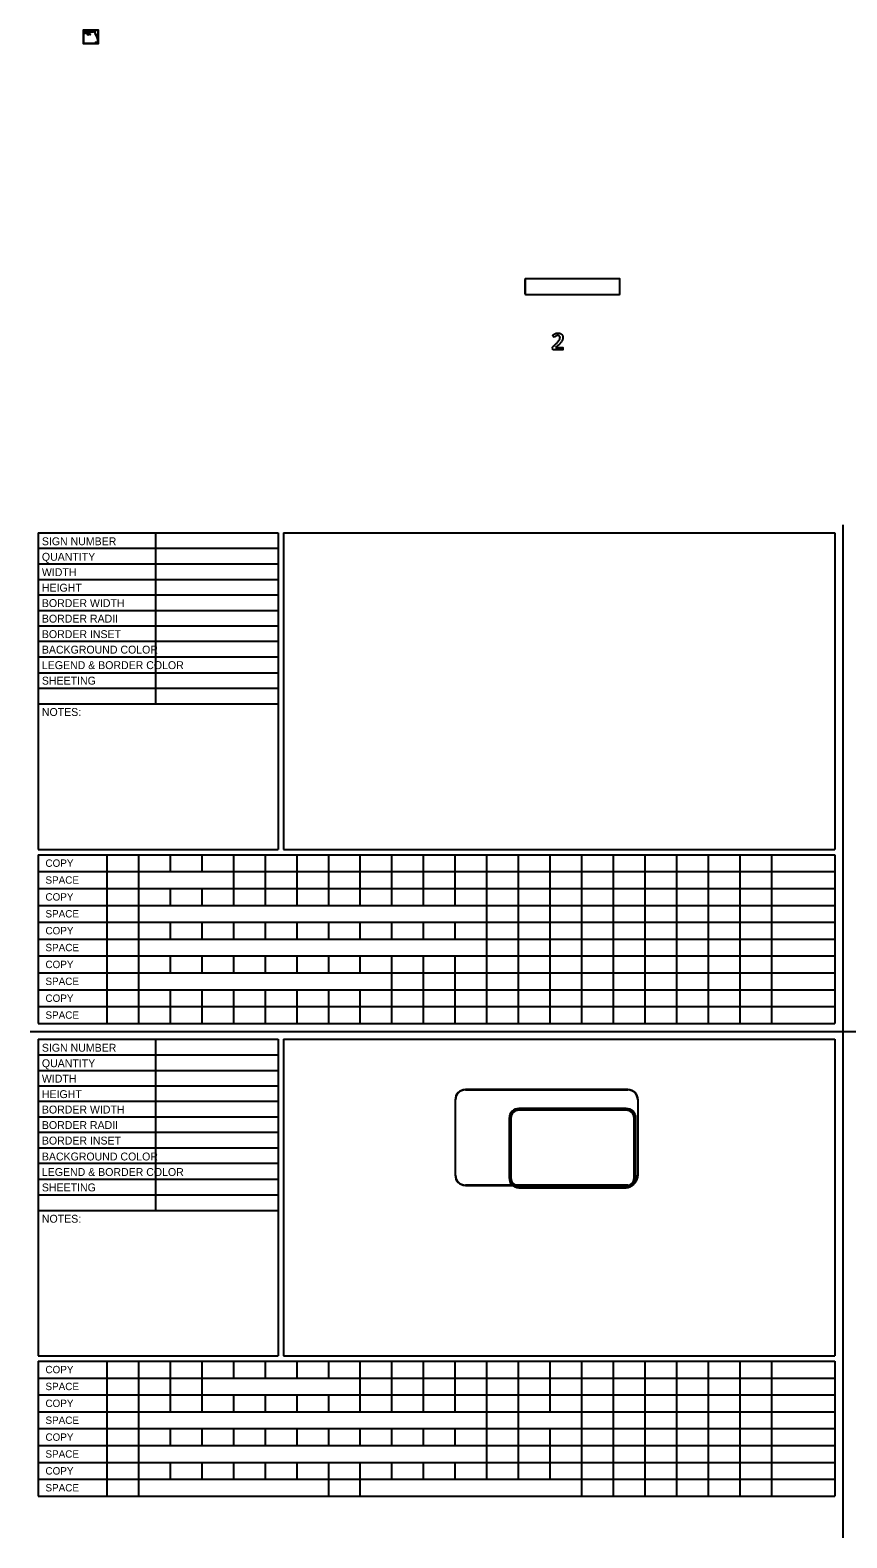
# Model space of a CAD drawing. Extents: x 10268197 to 10268511, y 2141503 to 2142677.
# Drawn here: x 10268317.7 to 10268395.1, y 2142380.3 to 2142523.2 of the extents above; entities that cross this region are included whole.
import ezdxf

# ---------------------------------------------------------------- set-up
doc = ezdxf.new("R2010")
doc.units = 0
for name, color, linetype in [('GSColorFill', 7, 'Continuous'), ('GSOutline', 7, 'Continuous'), ('SheetBorder_dp', 7, 'Continuous'), ('SumBoxLines_dp', 7, 'Continuous'), ('SumBoxLinesMin_dp', 7, 'Continuous'), ('TextMisc', 7, 'Continuous')]:
    doc.layers.add(name, color=color, linetype=linetype)

msp = doc.modelspace()

# ---------------------------------------------------------------- linework, layer by layer
at = {"layer": 'GSColorFill'}
for p, q in [((10268358, 2142421.8), (10268358, 2142414.65)), ((10268358, 2142421.8), (10268358, 2142414.65)), ((10268358.02, 2142414.65), (10268358.02, 2142421.8)), ((10268374.36, 2142422.76), (10268358.96, 2142422.76)), ((10268374.36, 2142422.76), (10268358.96, 2142422.76)), ((10268358.96, 2142422.73), (10268374.36, 2142422.73)), ((10268375.29, 2142421.8), (10268375.29, 2142414.65)), ((10268375.32, 2142414.65), (10268375.32, 2142421.8)), ((10268375.32, 2142414.65), (10268375.32, 2142421.8)), ((10268358.96, 2142413.68), (10268358.96, 2142413.71)), ((10268374.36, 2142413.71), (10268358.96, 2142413.71)), ((10268358.96, 2142413.71), (10268358.96, 2142413.68)), ((10268358.96, 2142413.68), (10268374.36, 2142413.68)), ((10268358.96, 2142413.68), (10268374.36, 2142413.68))]:
    msp.add_line(p, q, dxfattribs=at)
for centre, radius, start, end in [((10268358.96, 2142421.8), 0.963, 90, 180), ((10268358.96, 2142421.8), 0.963, 90, 180), ((10268358.96, 2142421.8), 0.935, 90, 180), ((10268374.36, 2142421.8), 0.963, 0, 90), ((10268374.36, 2142421.8), 0.963, 0, 90), ((10268374.36, 2142421.8), 0.935, 0, 90), ((10268358.96, 2142414.65), 0.963, 180, 270), ((10268358.96, 2142414.65), 0.963, 180, 270), ((10268358.96, 2142414.65), 0.935, 180, 270), ((10268374.36, 2142414.65), 0.963, 270, 0), ((10268374.36, 2142414.65), 0.963, 270, 0), ((10268374.36, 2142414.65), 0.935, 270, 0)]:
    msp.add_arc(centre, radius, start, end, dxfattribs=at)
at = {"layer": 'GSOutline'}
for p, q in [((10268322.74, 2142523.14), (10268322.74, 2142521.96)), ((10268322.75, 2142523.14), (10268322.75, 2142521.96)), ((10268324.17, 2142523.18), (10268322.78, 2142523.18)), ((10268324.17, 2142523.17), (10268322.78, 2142523.17)), ((10268324.21, 2142521.96), (10268324.21, 2142523.14)), ((10268324.21, 2142521.96), (10268324.21, 2142523.14)), ((10268322.78, 2142521.92), (10268324.17, 2142521.92)), ((10268322.78, 2142521.91), (10268324.17, 2142521.91)), ((10268364.61, 2142499.54), (10268364.61, 2142498.2)), ((10268364.63, 2142499.54), (10268364.63, 2142498.2)), ((10268373.53, 2142499.62), (10268364.7, 2142499.62)), ((10268373.53, 2142499.6), (10268364.7, 2142499.6)), ((10268373.59, 2142498.2), (10268373.59, 2142499.54)), ((10268373.61, 2142498.2), (10268373.61, 2142499.54)), ((10268364.7, 2142498.14), (10268373.53, 2142498.14)), ((10268364.7, 2142498.12), (10268373.53, 2142498.12)), ((10268363.11, 2142420.06), (10268363.11, 2142414.39)), ((10268363.28, 2142420.06), (10268363.28, 2142414.39)), ((10268374.2, 2142420.98), (10268364.03, 2142420.98)), ((10268374.2, 2142420.81), (10268364.03, 2142420.81)), ((10268374.95, 2142414.39), (10268374.95, 2142420.06)), ((10268375.12, 2142414.39), (10268375.12, 2142420.06)), ((10268364.03, 2142413.64), (10268374.2, 2142413.64)), ((10268364.03, 2142413.47), (10268374.2, 2142413.47))]:
    msp.add_line(p, q, dxfattribs=at)
for points in [[(10268322.78, 2142523.14), (10268322.78, 2142521.96), (10268324.17, 2142521.96), (10268324.17, 2142523.14)], [(10268323.88, 2142521.99), (10268323.94, 2142521.96), (10268324.02, 2142521.97), (10268324.14, 2142522.1), (10268324.14, 2142522.28), (10268324.09, 2142522.5), (10268324.01, 2142522.62), (10268324.02, 2142522.68), (10268323.93, 2142522.83), (10268323.87, 2142523.11), (10268323.74, 2142523.11), (10268323.72, 2142523.08), (10268323.26, 2142523.08), (10268323.25, 2142523.12), (10268322.81, 2142523.14), (10268322.82, 2142522.9), (10268322.94, 2142522.89), (10268322.97, 2142522.91), (10268323.1, 2142522.85), (10268323.2, 2142522.74), (10268323.34, 2142522.8), (10268323.42, 2142522.75), (10268323.44, 2142522.79), (10268323.35, 2142522.85), (10268323.22, 2142522.8), (10268323.13, 2142522.88), (10268322.97, 2142522.95), (10268322.93, 2142522.94), (10268322.87, 2142522.94), (10268322.85, 2142523.09), (10268323.21, 2142523.08), (10268323.23, 2142523.03), (10268323.74, 2142523.03), (10268323.76, 2142523.07), (10268323.84, 2142523.07), (10268323.89, 2142522.81), (10268323.97, 2142522.67), (10268323.97, 2142522.61), (10268324.05, 2142522.48), (10268324.1, 2142522.28), (10268324.1, 2142522.11), (10268324, 2142522.01), (10268323.95, 2142522), (10268323.91, 2142522.03)]]:
    msp.add_lwpolyline(points, close=True, dxfattribs=at)
for points in [[(10268367.25, 2142492.88), (10268367.21, 2142493.13)], [(10268367.38, 2142494.04), (10268367.23, 2142494.24)], [(10268367.51, 2142493.11), (10268368.21, 2142493.11), (10268368.21, 2142492.88), (10268367.25, 2142492.88)]]:
    msp.add_lwpolyline(points, dxfattribs=at)
for centre, radius, start, end in [((10268322.78, 2142523.14), 0.0439, 90, 180), ((10268322.78, 2142523.14), 0.0352, 90, 180), ((10268324.17, 2142523.14), 0.0439, 0, 90), ((10268324.17, 2142523.14), 0.0352, 0, 90), ((10268322.78, 2142521.96), 0.0439, 180, 270), ((10268322.78, 2142521.96), 0.0352, 180, 270), ((10268324.17, 2142521.96), 0.0352, 270, 0), ((10268324.17, 2142521.96), 0.0439, 270, 0), ((10268364.7, 2142499.54), 0.0833, 90, 180), ((10268364.7, 2142499.54), 0.0625, 90, 180), ((10268373.53, 2142499.54), 0.0833, 0, 90), ((10268373.53, 2142499.54), 0.0625, 0, 90), ((10268364.7, 2142498.2), 0.0833, 180, 270), ((10268364.7, 2142498.2), 0.0625, 180, 270), ((10268373.53, 2142498.2), 0.0833, 270, 0), ((10268373.53, 2142498.2), 0.0625, 270, 0), ((10268364.03, 2142420.06), 0.917, 90, 180), ((10268364.03, 2142420.06), 0.75, 90, 180), ((10268374.2, 2142420.06), 0.917, 0, 90), ((10268374.2, 2142420.06), 0.75, 0, 90), ((10268364.03, 2142414.39), 0.917, 180, 270), ((10268364.03, 2142414.39), 0.75, 180, 270), ((10268374.2, 2142414.39), 0.917, 270, 0), ((10268374.2, 2142414.39), 0.75, 270, 0)]:
    msp.add_arc(centre, radius, start, end, dxfattribs=at)
for points in [[(10268367.23, 2142494.24), (10268367.25, 2142494.26), (10268367.29, 2142494.3), (10268367.34, 2142494.34), (10268367.39, 2142494.37), (10268367.43, 2142494.39), (10268367.47, 2142494.41), (10268367.51, 2142494.43), (10268367.56, 2142494.44), (10268367.6, 2142494.45), (10268367.66, 2142494.46), (10268367.71, 2142494.46), (10268367.74, 2142494.47)], [(10268367.74, 2142494.47), (10268367.76, 2142494.46), (10268367.81, 2142494.46), (10268367.87, 2142494.45), (10268367.93, 2142494.44), (10268367.98, 2142494.42), (10268368.02, 2142494.4), (10268368.06, 2142494.37), (10268368.08, 2142494.36), (10268368.1, 2142494.34), (10268368.12, 2142494.31), (10268368.14, 2142494.28), (10268368.16, 2142494.25), (10268368.17, 2142494.22), (10268368.18, 2142494.2), (10268368.2, 2142494.15), (10268368.2, 2142494.1), (10268368.2, 2142494.06), (10268368.2, 2142494.04)], [(10268367.21, 2142493.13), (10268367.27, 2142493.18), (10268367.37, 2142493.27), (10268367.51, 2142493.41), (10268367.64, 2142493.53), (10268367.73, 2142493.63), (10268367.8, 2142493.72), (10268367.84, 2142493.78), (10268367.88, 2142493.84), (10268367.9, 2142493.88), (10268367.91, 2142493.91), (10268367.92, 2142493.96), (10268367.93, 2142494), (10268367.93, 2142494.02), (10268367.93, 2142494.03)], [(10268367.72, 2142494.23), (10268367.72, 2142494.23), (10268367.69, 2142494.23), (10268367.65, 2142494.23), (10268367.61, 2142494.21), (10268367.57, 2142494.2), (10268367.54, 2142494.18), (10268367.49, 2142494.15), (10268367.43, 2142494.1), (10268367.39, 2142494.06), (10268367.38, 2142494.04)], [(10268368.2, 2142494.04), (10268368.2, 2142494.02), (10268368.2, 2142493.97), (10268368.19, 2142493.91), (10268368.17, 2142493.84), (10268368.14, 2142493.78), (10268368.11, 2142493.71), (10268368.04, 2142493.62), (10268367.96, 2142493.52), (10268367.84, 2142493.4), (10268367.69, 2142493.26), (10268367.57, 2142493.16), (10268367.51, 2142493.11)], [(10268367.93, 2142494.03), (10268367.93, 2142494.03), (10268367.93, 2142494.05), (10268367.92, 2142494.08), (10268367.92, 2142494.1), (10268367.91, 2142494.12), (10268367.91, 2142494.13), (10268367.9, 2142494.15), (10268367.89, 2142494.16), (10268367.88, 2142494.17), (10268367.87, 2142494.18), (10268367.86, 2142494.19), (10268367.85, 2142494.2), (10268367.83, 2142494.21), (10268367.82, 2142494.22), (10268367.81, 2142494.22), (10268367.78, 2142494.23), (10268367.75, 2142494.23), (10268367.73, 2142494.23), (10268367.72, 2142494.23)]]:
    msp.add_open_spline(points, degree=3, dxfattribs=at)
at = {"layer": 'SheetBorder_dp'}
for p, q in [((10268394.73, 2142476.28), (10268394.73, 2142380.28)), ((10268317.73, 2142428.28), (10268471.73, 2142428.28))]:
    msp.add_line(p, q, dxfattribs=at)
at = {"layer": 'SumBoxLines_dp'}
for p, q in [((10268318.48, 2142475.53), (10268318.48, 2142445.53)), ((10268318.48, 2142475.53), (10268341.23, 2142475.53)), ((10268329.6, 2142475.53), (10268329.6, 2142459.34)), ((10268341.23, 2142475.53), (10268341.23, 2142445.53)), ((10268341.73, 2142475.53), (10268341.73, 2142445.53)), ((10268341.73, 2142475.53), (10268393.98, 2142475.53)), ((10268393.98, 2142475.53), (10268393.98, 2142445.53)), ((10268318.48, 2142474.07), (10268341.23, 2142474.07)), ((10268318.48, 2142472.59), (10268341.23, 2142472.59)), ((10268318.48, 2142471.12), (10268341.23, 2142471.12)), ((10268318.48, 2142469.66), (10268341.23, 2142469.66)), ((10268318.48, 2142468.19), (10268341.23, 2142468.19)), ((10268318.48, 2142466.73), (10268341.23, 2142466.73)), ((10268318.48, 2142465.26), (10268341.23, 2142465.26)), ((10268318.48, 2142463.79), (10268341.23, 2142463.79)), ((10268318.48, 2142462.28), (10268341.23, 2142462.28)), ((10268318.48, 2142460.81), (10268341.23, 2142460.81)), ((10268318.48, 2142459.34), (10268341.23, 2142459.34)), ((10268318.48, 2142445.53), (10268341.23, 2142445.53)), ((10268318.48, 2142445.03), (10268393.98, 2142445.03)), ((10268318.48, 2142445.03), (10268318.48, 2142429.03)), ((10268324.98, 2142445.03), (10268324.98, 2142429.03)), ((10268327.98, 2142445.03), (10268327.98, 2142429.03)), ((10268330.98, 2142445.03), (10268330.98, 2142443.43)), ((10268333.98, 2142445.03), (10268333.98, 2142443.43)), ((10268336.98, 2142445.03), (10268336.98, 2142441.83)), ((10268339.98, 2142445.03), (10268339.98, 2142441.83)), ((10268341.73, 2142445.53), (10268393.98, 2142445.53)), ((10268342.98, 2142445.03), (10268342.98, 2142441.83)), ((10268345.98, 2142445.03), (10268345.98, 2142441.83)), ((10268348.98, 2142445.03), (10268348.98, 2142441.83)), ((10268351.98, 2142445.03), (10268351.98, 2142443.43)), ((10268354.98, 2142445.03), (10268354.98, 2142443.43)), ((10268357.98, 2142445.03), (10268357.98, 2142443.43)), ((10268360.98, 2142445.03), (10268360.98, 2142441.83)), ((10268363.98, 2142445.03), (10268363.98, 2142441.83)), ((10268366.98, 2142445.03), (10268366.98, 2142441.83)), ((10268369.98, 2142445.03), (10268369.98, 2142441.83)), ((10268372.98, 2142445.03), (10268372.98, 2142443.43)), ((10268375.98, 2142445.03), (10268375.98, 2142443.43)), ((10268378.98, 2142445.03), (10268378.98, 2142443.43)), ((10268381.98, 2142445.03), (10268381.98, 2142443.43)), ((10268384.98, 2142445.03), (10268384.98, 2142443.43)), ((10268387.98, 2142445.03), (10268387.98, 2142443.43)), ((10268393.98, 2142445.03), (10268393.98, 2142429.03)), ((10268351.98, 2142443.43), (10268351.98, 2142440.23)), ((10268354.98, 2142443.43), (10268354.98, 2142440.23)), ((10268357.98, 2142443.43), (10268357.98, 2142440.23)), ((10268372.98, 2142443.43), (10268372.98, 2142429.03)), ((10268375.98, 2142443.43), (10268375.98, 2142429.03)), ((10268378.98, 2142443.43), (10268378.98, 2142437.03)), ((10268381.98, 2142443.43), (10268381.98, 2142437.03)), ((10268384.98, 2142443.43), (10268384.98, 2142437.03)), ((10268387.98, 2142443.43), (10268387.98, 2142429.03)), ((10268318.48, 2142441.83), (10268393.98, 2142441.83)), ((10268330.98, 2142441.83), (10268330.98, 2142440.23)), ((10268333.98, 2142441.83), (10268333.98, 2142440.23)), ((10268336.98, 2142441.83), (10268336.98, 2142440.23)), ((10268339.98, 2142441.83), (10268339.98, 2142440.23)), ((10268342.98, 2142441.83), (10268342.98, 2142440.23)), ((10268345.98, 2142441.83), (10268345.98, 2142440.23)), ((10268348.98, 2142441.83), (10268348.98, 2142440.23)), ((10268360.98, 2142441.83), (10268360.98, 2142438.63)), ((10268363.98, 2142441.83), (10268363.98, 2142438.63)), ((10268366.98, 2142441.83), (10268366.98, 2142437.03)), ((10268369.98, 2142441.83), (10268369.98, 2142437.03)), ((10268318.48, 2142438.63), (10268393.98, 2142438.63)), ((10268330.98, 2142438.63), (10268330.98, 2142437.03)), ((10268333.98, 2142438.63), (10268333.98, 2142437.03)), ((10268336.98, 2142438.63), (10268336.98, 2142437.03)), ((10268339.98, 2142438.63), (10268339.98, 2142437.03)), ((10268342.98, 2142438.63), (10268342.98, 2142437.03)), ((10268345.98, 2142438.63), (10268345.98, 2142437.03)), ((10268348.98, 2142438.63), (10268348.98, 2142437.03)), ((10268351.98, 2142438.63), (10268351.98, 2142437.03)), ((10268354.98, 2142438.63), (10268354.98, 2142437.03)), ((10268357.98, 2142438.63), (10268357.98, 2142437.03)), ((10268360.98, 2142438.63), (10268360.98, 2142429.03)), ((10268363.98, 2142438.63), (10268363.98, 2142429.03)), ((10268366.98, 2142437.03), (10268366.98, 2142429.03)), ((10268369.98, 2142437.03), (10268369.98, 2142429.03)), ((10268378.98, 2142437.03), (10268378.98, 2142429.03)), ((10268381.98, 2142437.03), (10268381.98, 2142429.03)), ((10268384.98, 2142437.03), (10268384.98, 2142429.03)), ((10268318.48, 2142435.43), (10268393.98, 2142435.43)), ((10268330.98, 2142435.43), (10268330.98, 2142433.83)), ((10268333.98, 2142435.43), (10268333.98, 2142433.83)), ((10268336.98, 2142435.43), (10268336.98, 2142433.83)), ((10268339.98, 2142435.43), (10268339.98, 2142433.83)), ((10268342.98, 2142435.43), (10268342.98, 2142433.83)), ((10268345.98, 2142435.43), (10268345.98, 2142433.83)), ((10268348.98, 2142435.43), (10268348.98, 2142433.83)), ((10268351.98, 2142435.43), (10268351.98, 2142429.03)), ((10268354.98, 2142435.43), (10268354.98, 2142429.03)), ((10268357.98, 2142435.43), (10268357.98, 2142429.03)), ((10268318.48, 2142432.23), (10268393.98, 2142432.23)), ((10268330.98, 2142432.23), (10268330.98, 2142429.03)), ((10268333.98, 2142432.23), (10268333.98, 2142429.03)), ((10268336.98, 2142432.23), (10268336.98, 2142429.03)), ((10268339.98, 2142432.23), (10268339.98, 2142429.03)), ((10268342.98, 2142432.23), (10268342.98, 2142429.03)), ((10268345.98, 2142432.23), (10268345.98, 2142429.03)), ((10268348.98, 2142432.23), (10268348.98, 2142429.03)), ((10268318.48, 2142429.03), (10268393.98, 2142429.03)), ((10268318.48, 2142427.53), (10268318.48, 2142397.53)), ((10268318.48, 2142427.53), (10268341.23, 2142427.53)), ((10268329.6, 2142427.53), (10268329.6, 2142411.31)), ((10268341.23, 2142427.53), (10268341.23, 2142397.53)), ((10268341.73, 2142427.53), (10268341.73, 2142397.53)), ((10268341.73, 2142427.53), (10268393.98, 2142427.53)), ((10268393.98, 2142427.53), (10268393.98, 2142397.53)), ((10268318.48, 2142426.07), (10268341.23, 2142426.07)), ((10268318.48, 2142424.59), (10268341.23, 2142424.59)), ((10268318.48, 2142423.12), (10268341.23, 2142423.12)), ((10268318.48, 2142421.66), (10268341.23, 2142421.66)), ((10268318.48, 2142420.19), (10268341.23, 2142420.19)), ((10268318.48, 2142418.73), (10268341.23, 2142418.73)), ((10268318.48, 2142417.26), (10268341.23, 2142417.26)), ((10268318.48, 2142415.79), (10268341.23, 2142415.79)), ((10268318.48, 2142414.28), (10268341.23, 2142414.28)), ((10268318.48, 2142412.8), (10268341.23, 2142412.8)), ((10268318.48, 2142411.31), (10268341.23, 2142411.31)), ((10268318.48, 2142397.53), (10268341.23, 2142397.53)), ((10268341.73, 2142397.53), (10268393.98, 2142397.53)), ((10268318.48, 2142397.03), (10268393.98, 2142397.03)), ((10268318.48, 2142397.03), (10268318.48, 2142384.23)), ((10268324.98, 2142397.03), (10268324.98, 2142384.23)), ((10268327.98, 2142397.03), (10268327.98, 2142384.23)), ((10268330.98, 2142397.03), (10268330.98, 2142393.83)), ((10268333.98, 2142397.03), (10268333.98, 2142393.83)), ((10268336.98, 2142397.03), (10268336.98, 2142395.43)), ((10268339.98, 2142397.03), (10268339.98, 2142395.43)), ((10268342.98, 2142397.03), (10268342.98, 2142395.43)), ((10268345.98, 2142397.03), (10268345.98, 2142395.43)), ((10268348.98, 2142397.03), (10268348.98, 2142393.83)), ((10268351.98, 2142397.03), (10268351.98, 2142393.83)), ((10268354.98, 2142397.03), (10268354.98, 2142393.83)), ((10268357.98, 2142397.03), (10268357.98, 2142395.43)), ((10268360.98, 2142397.03), (10268360.98, 2142395.43)), ((10268363.98, 2142397.03), (10268363.98, 2142393.83)), ((10268366.98, 2142397.03), (10268366.98, 2142393.83)), ((10268369.98, 2142397.03), (10268369.98, 2142395.43)), ((10268372.98, 2142397.03), (10268372.98, 2142395.43)), ((10268375.98, 2142397.03), (10268375.98, 2142395.43)), ((10268378.98, 2142397.03), (10268378.98, 2142395.43)), ((10268381.98, 2142397.03), (10268381.98, 2142395.43)), ((10268384.98, 2142397.03), (10268384.98, 2142395.43)), ((10268387.98, 2142397.03), (10268387.98, 2142395.43)), ((10268393.98, 2142397.03), (10268393.98, 2142384.23)), ((10268357.98, 2142395.43), (10268357.98, 2142392.23)), ((10268360.98, 2142395.43), (10268360.98, 2142387.43)), ((10268363.98, 2142395.43), (10268363.98, 2142387.43)), ((10268366.98, 2142395.43), (10268366.98, 2142392.23)), ((10268369.98, 2142395.43), (10268369.98, 2142389.03)), ((10268372.98, 2142395.43), (10268372.98, 2142384.23)), ((10268375.98, 2142395.43), (10268375.98, 2142384.23)), ((10268378.98, 2142395.43), (10268378.98, 2142389.03)), ((10268381.98, 2142395.43), (10268381.98, 2142389.03)), ((10268384.98, 2142395.43), (10268384.98, 2142389.03)), ((10268387.98, 2142395.43), (10268387.98, 2142384.23)), ((10268318.48, 2142393.83), (10268393.98, 2142393.83)), ((10268330.98, 2142393.83), (10268330.98, 2142392.23)), ((10268333.98, 2142393.83), (10268333.98, 2142392.23)), ((10268336.98, 2142393.83), (10268336.98, 2142392.23)), ((10268339.98, 2142393.83), (10268339.98, 2142392.23)), ((10268342.98, 2142393.83), (10268342.98, 2142392.23)), ((10268345.98, 2142393.83), (10268345.98, 2142392.23)), ((10268348.98, 2142393.83), (10268348.98, 2142392.23)), ((10268351.98, 2142393.83), (10268351.98, 2142392.23)), ((10268354.98, 2142393.83), (10268354.98, 2142392.23)), ((10268318.48, 2142390.63), (10268393.98, 2142390.63)), ((10268330.98, 2142390.63), (10268330.98, 2142389.03)), ((10268333.98, 2142390.63), (10268333.98, 2142389.03)), ((10268336.98, 2142390.63), (10268336.98, 2142389.03)), ((10268339.98, 2142390.63), (10268339.98, 2142389.03)), ((10268342.98, 2142390.63), (10268342.98, 2142389.03)), ((10268345.98, 2142390.63), (10268345.98, 2142389.03)), ((10268348.98, 2142390.63), (10268348.98, 2142389.03)), ((10268351.98, 2142390.63), (10268351.98, 2142389.03)), ((10268354.98, 2142390.63), (10268354.98, 2142389.03)), ((10268357.98, 2142390.63), (10268357.98, 2142389.03)), ((10268366.98, 2142390.63), (10268366.98, 2142389.03)), ((10268366.98, 2142389.03), (10268366.98, 2142385.83)), ((10268369.98, 2142389.03), (10268369.98, 2142384.23)), ((10268378.98, 2142389.03), (10268378.98, 2142384.23)), ((10268381.98, 2142389.03), (10268381.98, 2142384.23)), ((10268384.98, 2142389.03), (10268384.98, 2142384.23)), ((10268318.48, 2142387.43), (10268393.98, 2142387.43)), ((10268330.98, 2142387.43), (10268330.98, 2142385.83)), ((10268333.98, 2142387.43), (10268333.98, 2142385.83)), ((10268336.98, 2142387.43), (10268336.98, 2142385.83)), ((10268339.98, 2142387.43), (10268339.98, 2142385.83)), ((10268342.98, 2142387.43), (10268342.98, 2142385.83)), ((10268345.98, 2142387.43), (10268345.98, 2142384.23)), ((10268348.98, 2142387.43), (10268348.98, 2142384.23)), ((10268351.98, 2142387.43), (10268351.98, 2142385.83)), ((10268354.98, 2142387.43), (10268354.98, 2142385.83)), ((10268357.98, 2142387.43), (10268357.98, 2142385.83)), ((10268360.98, 2142387.43), (10268360.98, 2142385.83)), ((10268363.98, 2142387.43), (10268363.98, 2142385.83)), ((10268318.48, 2142384.23), (10268393.98, 2142384.23))]:
    msp.add_line(p, q, dxfattribs=at)
at = {"layer": 'SumBoxLinesMin_dp'}
for p, q in [((10268318.48, 2142443.43), (10268393.98, 2142443.43)), ((10268318.48, 2142440.23), (10268393.98, 2142440.23)), ((10268318.48, 2142437.03), (10268393.98, 2142437.03)), ((10268318.48, 2142433.83), (10268393.98, 2142433.83)), ((10268318.48, 2142430.63), (10268393.98, 2142430.63)), ((10268318.48, 2142395.43), (10268393.98, 2142395.43)), ((10268318.48, 2142392.23), (10268393.98, 2142392.23)), ((10268318.48, 2142389.03), (10268393.98, 2142389.03)), ((10268318.48, 2142385.83), (10268393.98, 2142385.83))]:
    msp.add_line(p, q, dxfattribs=at)

# ---------------------------------------------------------------- texts
at = {"layer": 'TextMisc'}
for s, height, p in [('SIGN NUMBER', 0.7476, (10268318.84, 2142474.36)), ('QUANTITY', 0.748, (10268318.84, 2142472.89)), ('WIDTH', 0.748, (10268318.84, 2142471.43)), ('HEIGHT', 0.748, (10268318.84, 2142469.96)), ('BORDER WIDTH', 0.7476, (10268318.84, 2142468.5)), ('BORDER RADII', 0.7476, (10268318.84, 2142467.03)), ('BORDER INSET', 0.7476, (10268318.84, 2142465.56)), ('BACKGROUND COLOR', 0.7476, (10268318.84, 2142464.09)), ('LEGEND & BORDER COLOR', 0.7476, (10268318.84, 2142462.62)), ('SHEETING', 0.748, (10268318.84, 2142461.15)), ('NOTES:', 0.748, (10268318.84, 2142458.18)), ('COPY', 0.7, (10268319.18, 2142443.88)), ('SPACE', 0.7, (10268319.18, 2142442.28)), ('COPY', 0.7, (10268319.18, 2142440.68)), ('SPACE', 0.7, (10268319.18, 2142439.08)), ('COPY', 0.7, (10268319.18, 2142437.48)), ('SPACE', 0.7, (10268319.18, 2142435.88)), ('COPY', 0.7, (10268319.18, 2142434.28)), ('SPACE', 0.7, (10268319.18, 2142432.68)), ('COPY', 0.7, (10268319.18, 2142431.08)), ('SPACE', 0.7, (10268319.18, 2142429.48)), ('SIGN NUMBER', 0.7476, (10268318.84, 2142426.36)), ('QUANTITY', 0.748, (10268318.84, 2142424.89)), ('WIDTH', 0.748, (10268318.84, 2142423.43)), ('HEIGHT', 0.748, (10268318.84, 2142421.96)), ('BORDER WIDTH', 0.7476, (10268318.84, 2142420.5)), ('BORDER RADII', 0.7476, (10268318.84, 2142419.03)), ('BORDER INSET', 0.7476, (10268318.84, 2142417.56)), ('BACKGROUND COLOR', 0.7476, (10268318.84, 2142416.05)), ('LEGEND & BORDER COLOR', 0.7476, (10268318.84, 2142414.58)), ('SHEETING', 0.748, (10268318.84, 2142413.12)), ('NOTES:', 0.748, (10268318.84, 2142410.15)), ('COPY', 0.7, (10268319.18, 2142395.88)), ('SPACE', 0.7, (10268319.18, 2142394.28)), ('COPY', 0.7, (10268319.18, 2142392.68)), ('SPACE', 0.7, (10268319.18, 2142391.08)), ('COPY', 0.7, (10268319.18, 2142389.48)), ('SPACE', 0.7, (10268319.18, 2142387.88)), ('COPY', 0.7, (10268319.18, 2142386.28)), ('SPACE', 0.7, (10268319.18, 2142384.68))]:
    msp.add_text(s, height=height, dxfattribs=at).set_placement(p)

doc.saveas('drawing.dxf')
